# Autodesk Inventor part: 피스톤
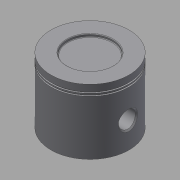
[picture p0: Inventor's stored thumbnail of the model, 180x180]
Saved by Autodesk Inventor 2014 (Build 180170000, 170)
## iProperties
Created: 2016-11
Part Number: 피스톤
Material: 강철, 탄소
Document SubType Name: Modeling
Designer: mduedu
Density: 7.87 g/cm^3
Appearance: 기본값
Mass: 273.349 g
Surface Area: 264.987 cm^2
Volume: 34.7331 cm^3
Author: mduedu
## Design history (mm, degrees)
sketch "스케치1"
  geometry: C1 r 30 at (0, 0); 1 further point
  constraints: 1 centre point, 1 coincident
  dimensions: "d0" = 60 diameter of C1
extrude "돌출1" new body sketch "스케치1" distance "d1" = 50; taper "d2" = 0 deg
sketch "스케치2"
  geometry: C1 r 28 at (0, 0); 1 further point
  constraints: 1 centre point, 1 coincident
  dimensions: "d3" = 56 diameter of C1
extrude "돌출2" cut sketch "스케치2" distance "d4" = 45; taper "d5" = 0 deg
sketch "스케치3"
  geometry: L1 (30, 0)-(30, 50) reference; L2 (30, 45)-(29, 45); L3 (29, 45)-(29, 44); L4 (29, 44)-(30, 44); L5 (30, 44)-(30, 45); L6 (30, 43)-(29, 43); L7 (29, 43)-(29, 42); L8 (29, 42)-(30, 42); L9 (30, 42)-(30, 43); L10 (30, 50)-(-30, 50) reference; L11 (0, 50)-(0, 0)
  constraints: 18 end point, 4 parallel, 3 equal length, 3 perpendicular, 2 horizontal, 2 point on line, 1 midpoint
  dimensions: "d6" = 1 distance of L2.start L2.end; "d8" = 5 distance between parallel lines of L10 L2; "d9" = 1 distance between parallel lines of L6 L4
revolve "회전1" sketch "스케치3" stored, may be unused: angle "d10" = 90 deg
node "작업 평면1"
sketch "스케치4"
  geometry: C1 r 10 at (20, 0); C2 r 6.5 at (20, 0); 1 further point
  constraints: 2 centre point, 1 coincident, 1 horizontal alignment
  dimensions: "d12" = 20 diameter of C1; "d13" = 13 diameter of C2; "d14" = 20 distance of point (0, 0) C1.centre
extrude "돌출3" join sketch "스케치4" stored distance "d15" = 11.75; taper "d16" = 0 deg
extrude "돌출4" cut sketch "스케치4" stored distance "d17" = 72; taper "d18" = 0 deg
fillet "모깎기1" dims "d19" = 3
fillet "모깎기2" dims "d20" = 3
chamfer "모따기1" distance "d21" = 1; stored, may be unused: second distance "d22" = 2, angle "d23" = 45 deg
chamfer "모따기2" distance "d24" = 1; stored, may be unused: second distance "d25" = 2, angle "d26" = 45 deg
sketch "스케치5"
  geometry: C1 r 17.5 at (0, 0); 1 further point
  constraints: 1 centre point, 1 coincident
  dimensions: "d27" = 35 diameter of C1
extrude "돌출5" cut sketch "스케치5" distance "d28" = 2; taper "d29" = 0 deg
fillet "모깎기3" dims "d30" = 0.5
node "솔리드1"
mirror "대칭1"
